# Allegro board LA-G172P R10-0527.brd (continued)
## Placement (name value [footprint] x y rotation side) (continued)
R175  10K_0201_5%  [R_0201]  124.49 15.81 90 bottom
R176  1K_0201_5%  [R_0201]  110.14 3.69 270 bottom
R178  10K_0201_5%  [R_0201]  126.02 16.39 270 bottom
R188  0_0201_5%  [R_0201]  110.9 15.12 270 bottom
R190  0_0201_5%  [R0201_0OHM]  107.35 15.12 270 bottom
R191  0_0201_5%  [R0201_0OHM]  108.19 15.12 270 bottom
R192  0_0201_5%  [R0201_0OHM]  110.22 15.12 270 bottom
R193  0_0201_5%  [R_0201]  125.25 14.54 90 bottom
R194  0_0201_5%  [R_0201]  126.02 14.54 90 bottom
R195  0_0201_5%  [R_0201]  126.78 14.54 90 bottom
R200  0_0402_5%  [R_0402]  206.67 4.98 0 top
R201  0_0201_5%  [R0201_0OHM]  108.87 3.69 270 bottom
R204  0_0603_5%  [R0603_0OHM]  202.15 15.21 90 top
R208  0_0201_5%  [R0201_0OHM]  57.35 16.48 180 bottom
R210  1K_0201_5%  [R_0201]  120.3 3.11 90 bottom
R211  0_0603_5%  [R0603_0OHM]  68.42 13.37 270 top
R213  0_0201_5%  [R0201_0OHM]  110.22 15.81 90 bottom
R216  0_0603_5%  [R0603_0OHM]  237.78 16.48 90 top
R220  100K_0201_5%  [R_0201]  174.72 64.83 90 top
R222  0_0402_5%  [R0402_0OHM]  176.25 70.25 90 top
R227  0_0603_5%  [R0603_0OHM]  21.35 24.53 225 top
R230  1K_0201_5%  [R_0201]  112.3 15.12 270 bottom
R231  1M_0402_5%  [R_0402]  97.06 68.32 90 top
R232  10K_0201_5%  [R_0201]  46.74 18.07 180 top
R236  0_0201_5%  [R_0201]  111.41 3.11 90 bottom
R238  2.2K_0201_1%  [R_0201]  132.43 80.94 90 bottom
R239  2.2K_0201_1%  [R_0201]  131.83 80.94 90 bottom
R244  0_0201_5%  [R0201_0OHM]  107.35 15.81 90 bottom
R245  100K_0201_5%  [R_0201]  129.13 80.72 270 bottom
R246  150_0201_1%  [R_0201]  112.3 16.39 270 bottom
R247  0_0201_5%  [R0201_0OHM]  108.24 3.69 270 bottom
R249  0_0201_5%  [R_0201]  124.43 3.69 270 bottom
R257  0_0201_5%  [R_0201]  119.03 3.11 90 bottom
R260  0_0201_5%  [R_0201]  116.49 3.11 90 bottom
R261  1.5K_0201_5%  [R_0201]  115.86 3.69 270 bottom
R267  1K_0201_5%  [R_0201]  119.67 3.69 270 bottom
R270  1K_0201_5%  [R_0201]  108.87 15.81 90 bottom
R271  75_0201_1%  [R_0201]  185.39 19.4 270 top
R272  330K_0201_1%  [R_0201]  206.63 60.04 90 bottom
R273  0_0201_5%  [R0201_0OHM]  205.01 60.6 0 bottom
R274  10K_0201_5%  [R_0201]  126.78 16.39 270 bottom
R283  1M_0201_5%  [R_0201]  207.86 60.62 180 bottom
R288  100K_0201_5%  [R_0201]  129.83 80.72 270 bottom
R300  0_0201_5%  [R0201_0OHM]  107.6 3.69 270 bottom
R311  1K_0201_5%  [R_0201]  122.21 3.11 90 bottom
R312  0_0201_5%  [R0201_0OHM]  108.19 15.81 90 bottom
R322  100K_0201_5%  [R_0201]  174.62 63.85 0 top
R335  0_0201_5%  [R_0201]  111.54 15.12 270 bottom
R360  0_0402_5%  [R_0402]  138.46 21.82 180 top
R374  100K_0201_5%  [R_0201]  203.42 10.3 270 top
R375  100K_0201_5%  [R_0201]  205.14 10.3 270 top
R390  0_0402_5%  [R_0402]  59.41 19.71 90 top
R410  100K_0201_5%  [R_0201]  111.54 16.39 270 bottom
R441  0_0603_5%  [R0603_0OHM]  190.15 52.17 180 top
R444  1K_0201_5%  [R_0201]  210.83 35.53 180 top
R445  1K_0201_5%  [R_0201]  210.83 34.9 180 top
R452  0_0201_5%  [R0201_0OHM]  195.8 25.84 90 top
R456  0_0201_5%  [R0201_0OHM]  199.49 52.08 270 top
R466  1K_0201_5%  [R_0201]  174.21 14.48 90 top
R470  0_0201_5%  [R0201_0OHM]  198.58 50.87 270 top
R471  0_0201_5%  [R_0201]  197.95 50.87 270 top
R529  75K_0201_5%  [R_0201]  177.77 64.58 90 bottom
R530  200_0201_1%  [R_0201]  204.02 55.15 0 bottom
R531  200_0201_1%  [R_0201]  203.33 55.15 180 bottom
R532  75K_0201_5%  [R_0201]  177.13 65.42 270 bottom
R533  0_0201_5%  [R0201_0OHM]  174.09 60.64 90 top
R534  0_0201_5%  [R_0201]  176.5 64.83 90 bottom
R544  0_0201_5%  [R_0201]  108.87 14.54 90 bottom
R545  0_0201_5%  [R_0201]  109.51 14.54 90 bottom
R600  10K_0201_5%  [R_0201]  44.89 18.07 0 top
R609  0_0201_5%  [R_0201]  210.24 33.63 0 top
R610  0_0201_5%  [R_0201]  195.17 25.84 90 top
R612  0.01_0402_1%  [R_0402]  161.49 76.26 0 bottom
R614  51_0201_5%  [R_0201]  134.97 27.44 270 bottom
R616  100K_0201_5%  [R_0201]  174.62 63.22 0 top
R617  20K_0201_5%  [R_0201]  174.09 62.5 270 top
R618  10K_0201_5%  [R_0201]  160.05 76.3 270 bottom
R620  0_0402_5%  [R0402_0OHM]  177.07 70.25 90 top
R621  10K_0201_5%  [R_0201]  122.09 79.83 0 bottom
R622  10K_0201_5%  [R_0201]  126.35 77.99 270 bottom
R623  200K_0201_5%  [R_0201]  126.92 77.4 90 bottom
R624  200K_0201_5%  [R_0201]  122.68 80.4 180 bottom
R626  0.01_0603_1%  [R_0603]  218.41 15.53 180 top
R627  47K_0201_5%  [R_0201]  123.35 78 180 bottom
R628  47K_0201_5%  [R_0201]  127.49 77.4 90 bottom
R629  100K_0201_5%  [R_0201]  60.26 11.97 180 top
R633  0_0201_5%  [R0201_0OHM]  90.28 65.07 90 top
R634  0_0402_5%  [R_0402]  162.39 75.38 180 bottom
R636  0_0201_5%  [R0201_0OHM]  66.29 18.93 0 top
R638  0_0402_5%  [R0402_0OHM]  60.17 19.71 90 top
R644  0_0201_5%  [R_0201]  117.13 3.11 90 bottom
R648  33_0201_5%  [R_0201]  215.44 6.79 90 top
R649  10K_0201_5%  [R_0201]  209.28 12.09 0 top
R651  0_0201_5%  [R0201_0OHM]  128.15 77.4 90 bottom
R652  0_0201_5%  [R0201_0OHM]  125.78 77.4 90 bottom
R655  0_0402_5%  [R_0402]  160.73 75.36 90 bottom
R656  10K_0201_5%  [R_0201]  215.44 5.56 90 top
R658  100K_0201_5%  [R_0201]  123.98 77.4 90 bottom
R660  51_0201_5%  [R_0201]  135.61 27.44 270 bottom
R666  100K_0201_5%  [R_0201]  265.23 25.59 270 top
R667  100K_0201_5%  [R_0201]  266.38 25.59 270 top
R669  0_0603_5%  [R0603_0OHM]  269.17 22.06 0 top
R670  0_0603_5%  [R0603_0OHM]  265.3 19.33 180 top
R672  0_0201_5%  [R0201_0OHM]  174.09 64.83 90 top
R677  1M_0201_5%  [R_0201]  125.19 77.99 270 bottom
R678  1M_0201_5%  [R_0201]  197.2 50.29 90 top
R679  1M_0201_5%  [R_0201]  210.37 42.01 0 top
R680  1M_0201_5%  [R_0201]  195.17 25.22 270 top
R681  1M_0201_5%  [R_0201]  210.24 32.99 0 top
R687  0_0402_5%  [R_0402]  206.67 4.19 0 top
R688  0_0402_5%  [R_0402]  206.67 11.71 0 top
R694  0_0402_5%  [R_0402]  171.93 65.96 180 top
R700  49.9_0201_1%  [R_0201]  216.08 20.57 270 bottom
R701  49.9_0201_1%  [R_0201]  215.5 20.57 270 bottom
R702  0_0201_5%  [R0201_0OHM]  214.29 20.59 270 bottom
R703  49.9_0201_1%  [R_0201]  212.44 20.57 270 bottom
R704  10K_0201_5%  [R_0201]  169.32 65.59 90 top
R709  10K_0201_5%  [R_0201]  157.7 77.85 90 bottom
R710  680_0201_5%  [R_0201]  159.23 80.45 90 bottom
R716  0_0805_5%  [R0805_0OHM]  42.79 14.26 180 top
R720  0_0402_5%  [R0402_0OHM]  171.93 67.18 180 top
R724  100K_0201_5%  [R_0201]  210.24 34.26 0 top
R725  0_0201_5%  [R_0201]  120.94 3.69 270 bottom
R726  0_0201_5%  [R_0201]  121.57 3.69 270 bottom
R747  0_0201_5%  [R0201_0OHM]  206.84 7.59 0 top
R787  0_0201_5%  [R0201_0OHM]  211.03 52.86 270 top
R789  150_0201_1%  [R_0201]  199.19 13.44 0 top
R800  0_0201_5%  [R0201_0OHM]  63.04 13.94 0 top
R801  0_0201_5%  [R_0201]  63.04 14.57 0 top
R808  0_0201_5%  [R0201_0OHM]  62.44 15.62 0 top
R931  2.1K_0402_1%  [R_0402]  90.19 66.74 180 top
R932  2.1K_0402_1%  [R_0402]  90.19 67.6 180 top
R1000  100K_0201_1%  [R_0201]  212.26 30.08 90 top
R1015  0_0201_5%  [R0201_0OHM]  131.83 79.25 90 bottom
R1016  0_0201_5%  [R0201_0OHM]  132.43 79.25 90 bottom
R1095  0_0402_5%  [R0402_0OHM]  189.88 44.59 0 top
R1096  0_0402_5%  [R0402_0OHM]  189.88 43.83 0 top
R1133  120K_0201_1%  [R_0201]  211.07 30.08 0 top
R1134  200K _0201_1%  [R_0201]  211.66 30.67 180 top
R1135  0_0201_1%  [R_0201]  211.08 29.5 0 top
R1136  100K_0201_1%  [R_0201]  212.26 28.9 90 top
R1141  100K_0201_1%  [R_0201]  196.93 4.66 180 top
R1142  100K_0201_1%  [R_0201]  197.66 5.32 270 top
R1143  100K_0201_1%  [R_0201]  198.83 4.8 180 top
R1150  0_0201_5%  [R0201_0OHM]  211.08 28.91 0 top
R2745  100K_0201_1%  [R_0201]  177.93 16.93 180 top
R2751  0_0402_5%  [R_0402]  179.05 11.15 180 top
R5717  0_0603_5%  [R0603_0OHM]  214.74 14.27 0 top
R5768  10K_0402_5%  [R_0402]  182.01 15.21 0 top
R5769  1M_0402_5%~D  [R_0402]  181.15 17.37 180 top
R5779  0_0402_5%  [R0402_0OHM]  179.42 17.42 90 top
R6048  0_0603_5%  [R0603_0OHM]  206.22 13.88 0 top
R6089  0_0402_5%  [R0402_0OHM]  275.17 26.71 0 top
R6090  0_0402_5%  [R0402_0OHM]  275.17 25.88 0 top
R6114  0_0201_5%  [R0201_0OHM]  161.07 77.85 90 bottom
R6115  0_0201_5%  [R0201_0OHM]  160.05 77.85 90 bottom
R6116  0_0201_5%  [R0201_0OHM]  155.53 80.08 90 bottom
R6117  0_0201_5%  [R0201_0OHM]  156.17 80.08 90 bottom
R6118  0_0201_5%  [R0201_0OHM]  157.7 80.45 90 bottom
R6128  2.2K_0201_5%  [R_0201]  160.05 79.77 270 bottom
R6129  2.2K_0201_5%  [R_0201]  161.07 79.77 270 bottom
R6133  0_0603_5%  [R0603_0OHM]  200.63 25.94 180 top
R6135  0_0603_5%  [R0603_0OHM]  187.61 16.8 0 top
R6136  0_0603_5%  [R_0603]  214.47 45.19 180 top
R6137  100K_0201_5%  [R_0201]  173.45 61.23 270 top
R6141  0_0201_5%  [R0201_0OHM]  154.67 80.19 90 bottom
R6142  0_0201_5%  [R0201_0OHM]  158.53 80.45 90 bottom
R6143  1K_0201_5%  [R_0201]  109.51 15.81 90 bottom
R6152  0_0201_5%  [R0201_0OHM]  204.86 50.27 180 top
R6155  0_0201_5%  [R_0201]  178.11 58.27 0 bottom
R6157  10K_0201_5%  [R_0201]  157.7 79.77 270 bottom
R6161  0_0603_5%  [R0603_0OHM]  170.78 69.25 90 top
R6162  10K_0201_5%  [R_0201]  168.18 65.59 90 top
R6163  0_0201_5%  [R0201_0OHM]  168.75 65.59 90 top
R6164  0_0201_5%  [R0201_0OHM]  217.09 47.12 0 top
R6166  0_0201_5%  [R0201_0OHM]  206.89 25.88 180 top
R6168  0_0201_5%  [R_0201]  175.99 64.83 90 top
R6169  0_0201_5%  [R0201_0OHM]  245.03 17.74 180 top
R6170  0_0201_5%  [R0201_0OHM]  195.71 52.81 180 top
R6171  0_0201_5%  [R_0201]  265.81 25.59 270 top
R6172  4.7K_0201_5%  [R_0201]  179.2 33.88 180 bottom
R6173  4.7K_0201_5%  [R_0201]  179.2 33.25 180 bottom
R6174  4.7K_0201_5%  [R_0201]  183.65 41.38 180 bottom
R6175  4.7K_0201_5%  [R_0201]  183.65 40.74 180 bottom
R6181  0_0201_5%  [R0201_0OHM]  100.34 7.21 180 top
R6182  0_0603_5%  [R0603_0OHM]  94.65 5.69 180 top
R6183  100K_0201_5%  [R_0201]  188.44 10.98 90 top
R6184  100K_0201_5%  [R_0201]  217.09 46.52 0 top
R6185  100K_0201_5%  [R_0201]  206.89 26.52 180 top
R6193  0_0201_5%  [R0201_0OHM]  189.01 10.98 90 top
R6194  100K_0201_5%  [R_0201]  175.36 64.83 90 top
R6199  0_0201_5%  [R0201_0OHM]  271.05 20.53 180 top
R6204  100K_0201_5%  [R_0201]  175.06 16.86 0 top
R6205  0_0201_5%  [R_0201]  66.29 18.36 0 top
R6206  0_0201_5%  [R_0201]  67.53 18.35 90 top
R6207  0_0201_5%  [R_0201]  159.23 79.18 90 bottom
R6208  100K_0201_5%  [R_0201]  177.97 39.64 90 top
RA1  2.2K_0201_5%  [R_0201]  30.26 21.88 180 top
RA2  2.2K_0201_5%  [R_0201]  31.44 21.12 180 bottom
RA3  20_0201_1%  [R_0201]  14.79 69.47 180 top
RA6  20_0201_1%  [R_0201]  7.81 75.12 270 bottom
RA8  1K_0201_5%  [R_0201]  22.49 22.45 180 top
RA9  1K_0201_5%  [R_0201]  23.17 23.09 0 top
RA10  100K_0201_5%  [R_0201]  24.8 19.44 270 top
RA13  100K_0201_1%  [R_0201]  26.64 11.24 90 top
RA14  200K _0201_1%  [R_0201]  25.98 11.21 180 top
RA17  33_0201_5%  [R_0201]  34.77 13.66 270 top
RA18  0_0402_5%  [R0402_0OHM]  37.69 13.87 90 top
RA21  1K_0201_5%  [R_0201]  29.14 10.77 0 top
RA22  0_0402_5%  [R0402_0OHM]  20.47 62.51 45 bottom
RA23  0_0402_5%  [R0402_0OHM]  23.01 18.58 0 bottom
RA25  0_0402_5%  [R0402_0OHM]  35.28 15.71 90 bottom
RA27  0_0201_5%  [R0201_0OHM]  21.9 21.18 0 top
RA28  0_0201_5%  [R0201_0OHM]  23.17 20.55 0 top
RA29  0_0402_5%  [R0402_0OHM]  31.66 9.49 90 top
RA30  1K_0201_5%  [R_0201]  23.76 22.45 180 top
RA36  0_0402_5%  [R_0402]  33.32 10.32 180 top
RA41  0_0402_5%  [R_0402]  36.93 13.87 90 top
RA57  100K_0201_5%  [R_0201]  29.73 10.2 180 top
RA58  0_0201_5%  [R0201_0OHM]  32.84 11.09 180 top
RA62  22_0201_5%  [R_0201]  32.84 11.97 180 top
RA63  0_0201_5%  [R_0201]  28.48 11.05 90 top
RA64  10K_0201_5%  [R_0201]  28.1 21.14 90 top
RA65  10K_0201_5%  [R_0201]  6.29 6.95 180 top
RA66  0_0201_5%  [R_0201]  28.48 9.84 90 top
RC1  150_0201_1%  [R_0201]  145.28 22.13 0 top
RC2  49.9_0201_1%  [R_0201]  137.38 26.86 90 bottom
RC3  150_0201_1%  [R_0201]  133.32 24.57 90 bottom
RC8  100_0201_1%  [R_0201]  122.93 23.87 180 top
RC12  100_0201_1%  [R_0201]  130.02 50.1 90 top
RC13  100_0201_1%  [R_0201]  130.65 50.1 90 top
RC14  100_0201_1%  [R_0201]  129.26 50.1 90 top
RC15  150_0201_1%  [R_0201]  172.65 45.69 0 bottom
RC16  200_0201_1%  [R_0201]  164.31 41.54 270 bottom
RC17  200_0201_1%  [R_0201]  173.41 36.55 0 bottom
RC20  200_0201_1%  [R_0201]  159.99 45.02 90 bottom
RC120  0_0603_5%  [R0603_0OHM]  179.36 35.72 0 top
RC139  0_0603_5%  [R0603_0OHM]  171.74 60.81 180 top
RC145  51_0201_5%  [R_0201]  134.08 22.11 270 top
RC146  51_0201_5%  [R_0201]  130.91 26.73 90 bottom
RC147  100K_0201_5%  [R_0201]  221 45.07 180 top
RC150  100_0201_5%  [R_0201]  132.05 22.11 270 top
RC151  51_0201_5%  [R_0201]  131.48 22.11 270 top
RC165  0_0402_5%  [R_0402]  181.27 38.33 180 top
RC168  0_0402_5%  [R0402_0OHM]  181.27 39.09 180 top
RC180  51_0201_5%  [R_0201]  133.45 26.73 90 bottom
RC181  51_0201_5%  [R_0201]  132.81 26.73 90 bottom
RC201  51_0201_5%  [R_0201]  132.18 26.73 90 bottom
RC202  100_0201_5%  [R_0201]  129.76 22.11 270 top
RC203  51_0201_5%  [R_0201]  133.32 22.11 270 top
RC222  49.9K_0201_1%  [R_0201]  176.84 32.99 0 top
RC223  49.9K_0201_1%  [R_0201]  176.84 34.14 0 top
RC226  0_0201_5%  [R0201_0OHM]  149.19 15.56 90 top
RC244  10K_0201_5%  [R_0201]  185.35 32.99 0 top
RC247  1K_0201_5%  [R_0201]  172.35 18.26 180 top
RC254  0_0201_5%  [R_0201]  158.64 47.76 270 bottom
RC255  0_0201_5%  [R0201_0OHM]  159.2 47.76 270 bottom
RC336  10_0201_1%  [R_0201]  162.78 50.1 90 top
RC338  10K_0201_5%  [R_0201]  160.43 47.42 180 bottom
RC339  10K_0201_5%  [R_0201]  158.08 47.76 270 bottom
RC344  51_0201_5%  [R_0201]  132.68 22.11 270 top
RC351  0_0201_5%  [R_0201]  147.04 21.14 90 top
RC367  10_0201_1%  [R_0201]  160.88 50.1 90 top
RC368  10_0201_1%  [R_0201]  161.51 50.1 90 top
RC369  10_0201_1%  [R_0201]  162.15 50.1 90 top
RC430  0_0201_5%  [R0201_0OHM]  186.43 33.97 90 top
RC432  1K_0201_5%  [R_0201]  185.86 33.97 90 top
RC433  8.2K_0201_5%  [R_0201]  187.13 32.36 0 top
RC434  8.2K_0201_5%  [R_0201]  189.45 31.77 90 top
RC503  22_0201_1%  [R_0201]  194.06 61.31 180 bottom
RC504  22_0201_1%  [R_0201]  194.06 61.95 180 bottom
RC505  0_0402_5%  [R0402_0OHM]  214.99 18.32 180 top
RC508  1M_0201_5%  [R_0201]  214.13 17.6 0 top
RC569  49.9_0201_1%  [R_0201]  162.4 49.97 270 bottom
RC582  0_0402_5%  [R_0402]  177.77 37.25 180 bottom
RC583  0_0402_5%  [R0402_0OHM]  174.95 37.6 0 bottom
RC587  0_0603_5%  [R0603_0OHM]  181.9 33.06 90 top
RC589  0.1_0402_1%  [R_0402]  178.4 35.46 90 top
RC592  0_0603_5%  [R0603_0OHM]  137.7 19.66 0 top
RC595  100K_0201_5%  [R_0201]  177.93 32.61 180 bottom
RC601  0_0201_5%  [R0201_0OHM]  111.94 20.04 0 top
RC602  56_0201_5%  [R_0201]  110.74 20.04 0 top
RC603  0_0201_5%  [R0201_0OHM]  111.94 19.34 0 top
RC604  100_0201_1%  [R_0201]  110.74 19.34 0 top
RC605  0_0201_5%  [R0201_0OHM]  111.94 20.74 0 top
RC606  100_0201_5%  [R_0201]  110.74 20.74 0 top
RC609  10K_0201_5%  [R_0201]  138.45 3.5 90 top
RC610  10K_0201_5%  [R_0201]  137.86 3.5 90 top
RC611  10K_0201_5%  [R_0201]  139.03 3.5 90 top
RC612  10K_0201_5%  [R_0201]  137.28 3.5 90 top
RC614  499_0201_1%  [R_0201]  125.13 20.57 90 top
RC615  100K_0201_5%  [R_0201]  185.83 27.56 90 top
RC616  100K_0201_5%  [R_0201]  189.45 28.71 270 top
RC617  100K_0201_5%  [R_0201]  187.71 31.72 180 top
RC619  0_0201_5%  [R0201_0OHM]  110.55 20.29 0 bottom
RC623  0_0201_5%  [R_0201]  111.82 19.53 0 bottom
RC624  0_0201_5%  [R0201_0OHM]  181.92 39.85 0 top
RC626  100K_0201_5%  [R_0201]  111.82 20.29 0 bottom
RC627  0_0201_5%  [R_0201]  185.77 38.49 270 top
RC630  0_0603_5%  [R0603_0OHM]  135.16 19.66 0 top
RC631  100K_0201_5%  [R_0201]  149.83 16.14 270 top
RC634  0_0201_5%  [R_0201]  153.51 17.46 90 top
RC636  0_0201_5%  [R0201_0OHM]  153.51 19.32 270 top
RC639  0_0603_5%  [R0603_0OHM]  129.76 16.93 90 top
RC640  0_0201_5%  [R0201_0OHM]  110.12 49.63 180 top
RC643  0_0603_5%  [R0603_0OHM]  105.7 46.2 0 top
RC644  0_0201_5%  [R_0201]  173.62 18.26 180 top
RC647  1K_0201_5%  [R_0201]  170.24 18.9 0 top
RC648  100K_0201_5%  [R_0201]  177.45 41.18 180 bottom
RC651  0_0201_5%  [R0201_0OHM]  203.99 9.71 90 top
RC655  49.9K_0201_1%  [R_0201]  176.84 34.71 0 top
RC656  49.9K_0201_1%  [R_0201]  176.84 33.56 0 top
RC657  0_0201_5%  [R0201_0OHM]  204.57 9.71 90 top
RC659  0_0603_5%  [R0603_0OHM]  128.43 20.1 0 top
RC663  10K_0201_5%  [R_0201]  141.12 6.46 90 top
RC664  10K_0201_5%  [R_0201]  140.53 6.46 90 top
RC665  1K_0201_5%  [R_0201]  186.41 46.94 270 bottom
RC666  1K_0201_5%  [R_0201]  187.04 46.94 270 bottom
RC667  1K_0201_5%  [R_0201]  173.13 53.61 270 bottom
RC668  1K_0201_5%  [R_0201]  172.56 53.61 270 bottom
RC671  10K_0201_5%  [R_0201]  169.77 35.47 270 bottom
RC672  1K_0201_5%  [R_0201]  179.42 40.23 180 top
RC673  1K_0201_5%  [R_0201]  179.42 40.87 180 top
RC679  10K_0201_5%  [R_0201]  177.93 41.5 180 top
RC680  10K_0201_5%  [R_0201]  179.33 41.5 180 top
RC682  10K_0201_5%  [R_0201]  159.35 49.8 270 bottom
RC683  0_0201_5%  [R0201_0OHM]  124.54 38.93 90 bottom
RC684  0_0201_5%  [R0201_0OHM]  124.54 40.13 90 bottom
RC685  0_0201_5%  [R0201_0OHM]  146.08 19.3 90 top
RC686  0_0201_5%  [R0201_0OHM]  145.51 19.3 90 top
RC687  10K_0201_5%  [R_0201]  161.26 43.57 270 bottom
RC688  0_0201_5%  [R0201_0OHM]  178.75 42.77 0 top
RC689  0_0201_5%  [R0201_0OHM]  159.35 42.33 0 bottom
RC690  0_0201_5%  [R0201_0OHM]  178.75 42.14 0 top
RC691  20K_0201_5%  [R_0201]  177.35 33.88 0 bottom
RC692  20K_0201_5%  [R_0201]  177.35 33.25 0 bottom
RC693  20K_0201_5%  [R_0201]  183.65 42.01 180 bottom
RC694  20K_0201_5%  [R_0201]  183.65 40.11 180 bottom
RC695  0_0201_5%  [R0201_0OHM]  190.34 49.92 270 top
RC696  0_0402_5%  [R0402_0OHM]  178.2 39.72 0 bottom
RC697  0_0201_5%  [R0201_0OHM]  177.73 53.69 0 top
RC698  0_0201_5%  [R_0201]  177.58 52.26 90 top
RC699  0_0201_5%  [R0201_0OHM]  177.01 52.26 90 top
RC700  100K_0201_5%  [R_0201]  109.86 20.29 180 bottom
RC701  100K_0201_5%  [R_0201]  154.3 19.66 0 top
RC702  0_0201_5%  [R0201_0OHM]  175.65 16.23 180 top
RC703  0_0201_5%  [R0201_0OHM]  175.65 15.59 180 top
RC704  0_0201_5%  [R0201_0OHM]  175.65 17.5 180 top
RC711  75K_0201_1%  [R_0201]  163.42 50.1 90 top
RC712  75K_0201_1%  [R_0201]  164.05 50.1 90 top
RC717  10K_0201_5%  [R_0201]  156.43 50.68 270 top
RC718  0_0603_5%  [R0603_0OHM]  147.8 21.44 0 top
RC723  10K_0201_5%  [R_0201]  134.08 28 90 bottom
RC724  10K_0201_5%  [R_0201]  134.08 27.32 270 bottom
RC727  0_0201_5%  [R_0201]  176.78 40.26 0 top
RC730  0_0201_5%  [R_0201]  152.85 15.66 180 top
RC731  0_0201_5%  [R0201_0OHM]  151.06 15.66 0 top
RC734  33_0201_5%  [R_0201]  165.83 44.64 270 bottom
RC735  100K_0201_5%  [R_0201]  184.12 35.79 180 top
RC736  0_0402_5%  [R0402_0OHM]  92.91 65.91 270 top
RC737  1M_0201_5%  [R_0201]  93.95 64.27 270 top
RC738  10K_0201_5%  [R_0201]  184.23 40.38 315 top
RC739  10K_0201_5%  [R_0201]  184.18 42.82 180 top
RC740  10K_0201_5%  [R_0201]  183.13 37.95 0 bottom
RC741  10K_0201_5%  [R_0201]  183.56 41.44 270 top
RC742  10K_0201_5%  [R_0201]  183.6 42.23 0 top
RC743  10K_0201_5%  [R_0201]  183.71 38.71 180 bottom
RC744  20K_0201_5%  [R_0201]  181.6 43.15 0 top
RC745  0_0402_5%  [R0402_0OHM]  236.51 16.94 270 top
RC746  0_0201_5%  [R_0201]  181.86 37.02 90 top
RC747  0_0402_5%  [R0402_0OHM]  167.9 43.22 0 bottom
RC748  0_0201_5%  [R_0201]  127.81 30.48 180 bottom
RC749  0_0201_5%  [R_0201]  123.4 24.04 45 bottom
RC750  0_0201_5%  [R_0201]  123.81 23.64 45 bottom
RC751  10K_0201_5%  [R_0201]  191.33 31.47 180 bottom
RC752  10K_0201_5%  [R_0201]  191.33 30.83 180 bottom
RD1  240_0201_1%  [R_0201]  159.16 52 90 top
RD2  240_0201_1%  [R_0201]  162.19 52.61 180 top
RD3  240_0201_1%  [R_0201]  130.88 71.08 270 top
RD4  240_0201_1%  [R_0201]  128.47 71.08 270 top
RD21  240_0201_1%  [R_0201]  148.34 52.55 180 top
RD22  240_0201_1%  [R_0201]  144.84 52.55 0 top
RD23  240_0201_1%  [R_0201]  113.51 71.19 270 top
RD24  240_0201_1%  [R_0201]  115.92 71 270 top
RD25  0_0201_5%  [R0201_0OHM]  167.65 58.39 180 top
RD26  0_0201_5%  [R_0201]  167.06 57.76 0 top
RD27  0_0201_5%  [R0201_0OHM]  167.65 63.35 180 top
RD28  0_0201_5%  [R_0201]  167.06 63.98 0 top
RD29  0_0201_5%  [R0201_0OHM]  153.35 58.46 0 top
RD30  0_0201_5%  [R_0201]  153.35 57.82 0 top
RD31  0_0201_5%  [R0201_0OHM]  153.35 64.36 0 top
RD32  0_0201_5%  [R_0201]  153.35 64.93 0 top
RD33  0_0201_5%  [R0201_0OHM]  123.26 65.47 270 top
RD34  0_0201_5%  [R_0201]  122.65 65.45 180 top
RD35  0_0201_5%  [R0201_0OHM]  123.29 59.27 90 top
RD36  0_0201_5%  [R_0201]  123.27 58.65 180 top
RD37  0_0201_5%  [R0201_0OHM]  108.43 63.51 270 top
RD38  0_0201_5%  [R_0201]  108.41 64.12 180 top
RD39  0_0201_5%  [R0201_0OHM]  108.43 60.17 90 top
RD40  0_0201_5%  [R_0201]  108.43 59.54 180 top
RD41  0_0201_5%  [R_0201]  81.92 71.22 180 top
RD42  0_0201_5%  [R0201_0OHM]  82.61 71.22 0 top
RD43  0_0201_5%  [R_0201]  92.22 65.67 270 top
RD44  0_0201_5%  [R_0201]  91.03 65.67 0 top
RD45  0_1206_5%  [R_1206]  103.92 60.81 0 top
RD46  0_1206_5%  [R_1206]  106.52 56.49 90 top
RD300  1M_0201_5%  [R_0201]  83.75 64.93 0 top
RD400  0_0402_5%  [R0402_0OHM]  82.88 65.07 90 top
RE1  10K_0201_5%  [R_0201]  204.86 55.09 180 top
RE10  0_0201_5%  [R_0201]  175.48 18.98 90 top
RE14  100K_0201_5%  [R_0201]  189.62 48.11 180 top
RE15  0_0201_5%  [R_0201]  187.76 48.11 0 top
RE21  100K_0201_5%  [R_0201]  189.03 48.74 0 top
RE22  0_0201_5%  [R_0201]  187.76 48.74 0 top
RE29  100K_0201_5%  [R_0201]  175.48 20.25 90 top
RE48  100K_0201_5%  [R_0201]  210.28 60.21 270 bottom
RE49  0_0603_5%  [R0603_0OHM]  202.92 58.84 90 top
RE87  100K_0201_5%  [R_0201]  198.34 53.66 90 top
RE93  10K_0201_5%  [R_0201]  203 55.09 0 top
RE95  100K_0201_5%  [R_0201]  203.04 63.5 90 top
RE96  100K_0201_5%  [R_0201]  219.59 55.35 180 top
RE97  100K_0201_5%  [R_0201]  207.76 60 270 bottom
RE98  100K_0201_5%  [R_0201]  210.41 64.32 90 bottom
RE99  100K_0201_5%  [R_0201]  214.85 62.62 270 bottom
RE100  100K_0201_5%  [R_0201]  215.87 62.62 270 bottom
RE101  100K_0201_5%  [R_0201]  215.23 64.27 270 bottom
RE102  100K_0201_5%  [R_0201]  214.6 64.27 270 bottom
RE106  0_0402_5%  [R0402_0OHM]  206.94 65.39 90 bottom
RE108  100K_0201_5%  [R_0201]  214.22 62.04 90 bottom
RE109  100K_0201_5%  [R_0201]  211.11 62.23 90 bottom
RE111  2.2K_0201_5%  [R_0201]  207.23 54.11 270 top
RE112  2.2K_0201_5%  [R_0201]  206.6 54.11 270 top
RE113  100_0201_5%  [R_0201]  203.17 62.04 90 top
RE115  43K_0402_1%  [R_0402]  208 53.24 90 top
RE122  100K_0201_5%  [R_0201]  216.55 53.53 90 top
RE123  100K_0201_5%  [R_0201]  219.46 63.93 180 top
RE124  10K_0201_1%  [R_0201]  216.42 64.87 180 bottom
RE125  300_0402_5%  [R_0402]  208.76 52.37 270 top
RE126  300_0402_5%  [R_0402]  208.76 54.15 270 top
RE130  100K_0201_5%  [R_0201]  215.87 64.27 270 bottom
RE133  100K_0201_5%  [R_0201]  203.72 64.74 180 top
RE137  100K_0201_5%  [R_0201]  210.03 68.13 90 top
RE142  100K_0201_5%  [R_0201]  209.39 68.13 90 top
RE147  0_0201_5%  [R0201_0OHM]  214.35 59.57 270 bottom
RE152  1K_0201_5%  [R_0201]  203.13 65.51 0 top
RE153  43_0402_5%  [R_0402]  218.97 57.31 0 top
RE154  100K_0201_5%  [R_0201]  204.99 65.51 180 top
RE156  100K_0201_5%  [R_0201]  219.01 53.44 0 top
RE157  100K_0201_5%  [R_0201]  200.97 61.19 0 top
RE158  100_0402_1%  [R_0402]  218.97 60.93 0 top
RE159  10K_0201_5%  [R_0201]  210.41 54.11 270 top
RE160  100K_0201_5%  [R_0201]  205.77 53.53 90 top
RE164  100_0201_1%  [R_0201]  218.88 50.52 0 top
RE172  33_0201_5%  [R_0201]  212.11 69.58 0 top
RE178  0_0402_5%  [R_0402]  208.58 68.17 180 top
RE183  10K_0201_1%  [R_0201]  201.18 67.54 180 top
RE184  100K_0201_5%  [R_0201]  201.61 64.49 0 top
RE185  0_0201_5%  [R0201_0OHM]  219.01 54.08 0 top
RE186  0_0201_5%  [R_0201]  204.4 57.25 0 top
RE187  1K_0201_5%  [R_0201]  201.61 63.85 0 top
RE193  0_0201_5%  [R_0201]  211.55 67.31 90 bottom
RE194  2K_0402_5%  [R_0402]  219.88 59.18 180 top
RE199  1.58K_0402_1%  [R_0402]  218.97 66.78 0 top
RE200  10_0201_1%  [R_0201]  229.52 2.39 0 top
RE201  10K_0201_5%  [R_0201]  226.26 10.29 270 top
RE202  10K_0201_5%  [R_0201]  227.94 10.41 270 top
RE203  10K_0201_5%  [R_0201]  227.38 10.41 270 top
RE204  100K_0201_5%  [R_0201]  229.65 10.41 270 top
RE205  10K_0201_5%  [R_0201]  229.08 9.83 90 top
RE206  0_0201_5%  [R_0201]  228.51 10.41 270 top
RE208  100K_0201_5%  [R_0201]  219.59 55.98 180 top
RE209  0_0201_5%  [R0201_0OHM]  226.82 9.7 90 top
RE210  10K_0201_5%  [R_0201]  230.21 9.83 90 top
RE211  10K_0201_5%  [R_0201]  230.77 9.83 90 top
RE212  10K_0201_5%  [R_0201]  231.34 9.83 90 top
RE213  10K_0201_5%  [R_0201]  231.91 9.55 90 top
RE215  8.2K_0201_1%  [R_0201]  201.56 60.58 180 top
RE219  2.2K_0201_5%  [R_0201]  197.71 56.96 90 top
RE237  100K_0201_5%  [R_0201]  64.22 15.62 180 top
RE244  100K_0201_5%  [R_0201]  210.66 68.13 90 top
RE245  0_0201_5%  [R_0201]  213.58 54.11 270 top
RE247  100K_0201_5%  [R_0201]  204.4 64.74 0 top
RE248  0_0201_5%  [R0201_0OHM]  212.69 61.28 90 bottom
RE305  0_0402_5%  [R0402_0OHM]  86.41 58.27 90 top
RE312  1M_0201_5%  [R_0201]  87.19 58.3 270 top
RE321  0_0201_1%  [R_0201]  176.66 62.46 180 top
RE322  0_0201_1%  [R_0201]  174.81 62.46 0 top
RE402  0_0402_5%  [R0402_0OHM]  212.85 25.61 90 top
RE405  0_0402_5%  [R0402_0OHM]  26.97 3.45 90 top
RE411  0_0402_5%  [R0402_0OHM]  213.43 52.36 0 top
RE412  1M_0201_5%  [R_0201]  212.06 26.68 270 top
RE417  0_0402_5%  [R0402_0OHM]  266.02 9.38 0 top
RE426  100K_0201_5%  [R_0201]  210.92 60.21 270 bottom
RE428  0_0201_5%  [R0201_0OHM]  210.98 67.31 90 bottom
RE431  0_0201_5%  [R0201_0OHM]  214.85 54.11 270 top
RE445  2.2K_0201_5%  [R_0201]  208.25 64.91 270 bottom
RE446  2.2K_0201_5%  [R_0201]  209.52 64.91 270 bottom
RE448  0_0201_5%  [R0201_0OHM]  204.86 55.85 180 top
RE449  100K_0201_5%  [R_0201]  207.87 61.28 90 bottom
RE451  10K_0201_1%  [R_0201]  199.49 50.87 270 top
RE457  0_0201_5%  [R_0201]  202.15 53.1 270 top
RE458  2.2K_0201_5%  [R_0201]  211.93 61.95 90 bottom
RE459  2.2K_0201_5%  [R_0201]  211.04 64.91 270 bottom
RE460  0_0201_5%  [R_0201]  187.32 45.06 0 top
RE461  0_0201_5%  [R0201_0OHM]  212.95 54.11 270 top
RE462  0_0201_5%  [R0201_0OHM]  209.65 70.29 90 top
RE463  0_0201_5%  [R0201_0OHM]  212.19 71 270 top
RE464  0_0201_5%  [R0201_0OHM]  202.15 53.78 90 top
RE467  0_0201_5%  [R0201_0OHM]  219.46 64.5 180 top
RE468  0_0201_5%  [R0201_0OHM]  219.46 65.13 180 top
RE469  100K_0201_5%  [R_0201]  210.47 62.23 90 bottom
RE470  100K_0201_5%  [R_0201]  208.88 64.91 270 bottom
RE471  0_0201_5%  [R0201_0OHM]  219.59 56.62 180 top
RE472  100K_0201_5%  [R_0201]  211.04 53.53 90 top
RE473  100K_0201_5%  [R_0201]  212.31 53.53 90 top
RE475  100K_0201_5%  [R_0201]  219.49 61.61 180 top
RE476  0_0201_5%  [R0201_0OHM]  215.41 53.53 90 top
RE477  0_0201_5%  [R0201_0OHM]  197.71 55.69 90 top
RE478  100K_0201_1%  [R_0201]  212.31 52.86 270 top
RE479  390K_0402_1%  [R_0402]  213.25 48.92 0 top
RE480  1M_0201_1%  [R_0201]  216.16 49 180 top
RE481  10K_0201_5%  [R_0201]  219.01 54.71 0 top
RE482  0_0201_5%  [R0201_0OHM]  217.33 53.53 90 top
RE483  2.2K_0201_5%  [R_0201]  211.93 63.69 90 bottom
RE484  2.2K_0201_5%  [R_0201]  212.57 63.69 90 bottom
RE485  0_0201_5%  [R_0201]  219.53 67.54 180 top
RE486  100K_0201_5%  [R_0201]  203.8 58.39 270 top
RE487  0_0201_5%  [R_0201]  204.99 56.5 180 top
RE488  100K_0201_5%  [R_0201]  142.87 7.04 270 top
RE489  0_0402_5%  [R0402_0OHM]  95.39 51.57 0 top
RE490  0_0402_5%  [R0402_0OHM]  200.56 6.14 180 top
RE491  1M_0201_5%  [R_0201]  198.83 5.42 180 top
RE492  0_0201_5%  [R0201_0OHM]  220.68 65.32 0 top
RE493  10K_0201_5%  [R_0201]  220.76 52.83 90 top
RE494  0_0201_5%  [R_0201]  204.73 67.92 180 top
RE520  10M_0201_1%  [R_0201]  217.58 72.43 180 top
RE521  100K_0201_5%  [R_0201]  214.78 72.43 0 top
RE522  100K_0201_5%  [R_0201]  211.69 52.86 270 top
RE523  0_0201_5%  [R_0201]  252.67 10.7 90 top
RE524  0_0201_5%  [R_0201]  252.67 11.9 90 top
RE525  240K_0402_5%  [R_0402]  204.82 66.32 90 top
RE526  100K_0201_5%  [R_0201]  214.51 60.21 90 bottom
RH1  100_0201_1%  [R_0201]  171.55 22.11 270 top
RH4  49.9_0201_1%  [R_0201]  159.99 43.57 270 bottom
RH5  49.9_0201_1%  [R_0201]  177.98 24.36 0 top
RH6  49.9_0201_1%  [R_0201]  125.17 31.07 270 bottom
RH7  49.9_0201_1%  [R_0201]  127.23 31.06 0 bottom
RH8  10K_0201_5%  [R_0201]  170.28 22.11 270 top
RH9  10K_0201_5%  [R_0201]  183.1 31.44 270 top
RH10  113_0201_1%  [R_0201]  170.91 22.11 270 top
RH11  0_0201_5%  [R0201_0OHM]  147.67 50.19 90 top
RH12  470_0201_1%  [R_0201]  167.65 58.96 180 top
RH13  0_0201_5%  [R0201_0OHM]  131.67 50.68 270 top
RH14  0_0201_5%  [R_0201]  177.49 30.59 0 top
RH15  0_0201_5%  [R_0201]  177.49 29.96 0 top
RH16  10M_0201_1%  [R_0201]  171.33 51.34 180 top
RH17  200K _0201_1%  [R_0201]  178.67 29.98 90 top
RH23  49.9_0201_1%  [R_0201]  216.66 19.99 90 bottom
RH24  49.9_0201_1%  [R_0201]  213.01 19.99 90 bottom
RH25  49.9_0201_1%  [R_0201]  214.92 19.99 90 bottom
RH26  49.9_0201_1%  [R_0201]  213.65 19.99 90 bottom
RH27  49.9_0201_1%  [R_0201]  212.11 21.52 90 bottom
RH39  10K_0201_5%  [R_0201]  182 42.01 180 bottom
RH40  10K_0201_5%  [R_0201]  182 40.11 180 bottom
RH41  10K_0201_5%  [R_0201]  182 40.74 180 bottom
RH42  0_0201_5%  [R0201_0OHM]  169.01 55.81 90 top
RH46  100K_0201_5%  [R_0201]  173.71 55.51 270 top
RH57  0_0201_5%  [R0201_0OHM]  165.07 45.31 90 bottom
RH64  1M_0201_1%  [R_0201]  172.65 46.33 0 bottom
RH80  49.9_0201_1%  [R_0201]  129.19 22.11 270 top
RH95  1K_0201_1%  [R_0201]  125.95 21.16 270 top
RH96  1K_0201_5%  [R_0201]  125.13 19.95 270 top
RH98  20K_0201_5%  [R_0201]  177.93 35.15 180 bottom
RH111  33_0201_1%  [R_0201]  163.74 48.14 270 bottom
RH112  33_0201_1%  [R_0201]  164.31 49.41 270 bottom
RH113  33_0201_1%  [R_0201]  163.7 49.41 270 bottom
RH114  75K_0201_5%  [R_0201]  195.13 56.49 0 top
RH129  10K_0201_5%  [R_0201]  180.6 37.18 180 bottom
RH139  10K_0201_5%  [R_0201]  176.84 37.57 0 top
RH141  100K_0201_5%  [R_0201]  169.01 45.27 90 bottom
RH142  4.7K_0201_5%  [R_0201]  168.4 45.27 90 bottom
RH143  499_0201_1%  [R_0201]  181.86 35.85 0 top
RH144  499_0201_1%  [R_0201]  181.86 36.42 0 top
RH145  10K_0201_5%  [R_0201]  180.6 37.95 180 bottom
RH185  10K_0201_5%  [R_0201]  176.84 35.85 0 top
RH200  10K_0201_5%  [R_0201]  180.6 42.01 180 bottom
RH201  10K_0201_5%  [R_0201]  179.36 42.77 270 bottom
RH202  10K_0201_5%  [R_0201]  184.88 42.77 180 bottom
RH203  10K_0201_5%  [R_0201]  183.1 42.77 0 bottom
RH207  0_0201_5%  [R0201_0OHM]  177.86 46.57 0 top
RH217  1K_0201_1%  [R_0201]  164.94 49.41 270 bottom
RH218  0_0201_5%  [R0201_0OHM]  164.92 50.68 270 bottom
RH280  0_0201_5%  [R0201_0OHM]  176.78 43.47 0 top
RH297  10K_0201_5%  [R_0201]  166.47 50.68 270 top
RH298  100K_0201_5%  [R_0201]  173.71 57.47 90 top
RH300  10K_0201_5%  [R_0201]  172.94 33.63 90 bottom
RH301  4.7K_0201_5%  [R_0201]  173.71 56.78 270 top
RH312  0_0201_5%  [R0201_0OHM]  165.89 50.1 90 top
RH460  100K_0201_5%  [R_0201]  169.01 50.1 90 top
RH475  60.4_0201_1%  [R_0201]  179.38 28.17 0 top
RH565  0_0402_5%  [R0402_0OHM]  199.87 66.32 90 top
RH572  20K_0201_5%  [R_0201]  178.51 50.96 180 top
RH573  20K_0201_5%  [R_0201]  169.9 50.68 270 bottom
RH575  1M_0201_1%  [R_0201]  178.72 48.75 270 top
RH584  0_0201_5%  [R0201_0OHM]  186.62 25.94 0 top
RH586  0_0201_5%  [R0201_0OHM]  188.48 25.94 180 top
RH587  60.4_0201_1%  [R_0201]  170.24 20.8 0 top
RH588  1K_0201_5%  [R_0201]  170.82 19.66 180 top
RH591  100K_0201_5%  [R_0201]  167.86 50.1 90 top
RH592  10K_0201_5%  [R_0201]  168.43 50.1 90 top
RH594  0_0201_5%  [R0201_0OHM]  175.99 34.43 270 bottom
RH595  1K_0201_5%  [R_0201]  157.23 19.91 180 top
RH600  0_0201_5%  [R0201_0OHM]  167.48 48.78 270 bottom
RH601  10K_0201_5%  [R_0201]  166.59 48.19 90 bottom
RH603  10K_0201_5%  [R_0201]  163.42 43.57 270 bottom
RH604  10K_0201_5%  [R_0201]  177.98 28.17 0 top
RH605  10K_0201_5%  [R_0201]  163.42 45.63 270 bottom
RH606  1K_0201_5%  [R_0201]  172.31 34.9 90 bottom
RH607  1K_0201_5%  [R_0201]  170.4 34.9 90 bottom
RH610  10K_0201_5%  [R_0201]  177.93 42.14 180 top
RH612  10K_0201_5%  [R_0201]  182 37.18 180 bottom
RH613  10K_0201_5%  [R_0201]  177.43 36.99 180 top
RH614  10K_0201_5%  [R_0201]  182 37.95 180 bottom
RH615  10K_0201_5%  [R_0201]  177.43 36.42 180 top
RH616  10K_0201_5%  [R_0201]  182 38.71 180 bottom
RH617  20K_0201_5%  [R_0201]  170.02 42.3 270 bottom
RH618  2.2K_0201_5%  [R_0201]  170.66 42.3 270 bottom
RH621  4.7K_0201_5%  [R_0201]  157.07 50.1 90 top
RH622  0_0201_5%  [R0201_0OHM]  142.84 81.53 90 bottom
RH625  0_0201_5%  [R0201_0OHM]  173.71 59.32 270 top
RH629  10K_0201_5%  [R_0201]  177.98 27.53 0 top
RH630  10K_0201_5%  [R_0201]  177.98 26.9 0 top
RH631  10K_0201_5%  [R_0201]  182 41.38 180 bottom
RH632  2.2K_0201_5%  [R_0201]  178.44 45.43 180 top
RH633  2.2K_0201_5%  [R_0201]  178.44 44.85 180 top
RH634  1K_0201_5%  [R_0201]  168.98 44.36 180 bottom
RH635  100K_0201_5%  [R_0201]  165.83 42.81 270 bottom
RH636  100K_0201_5%  [R_0201]  166.47 42.81 270 bottom
RH637  0_0201_5%  [R_0201]  170.11 52.17 0 top
RH638  0_0201_5%  [R0201_0OHM]  171.04 34.9 90 bottom
RH639  0_0201_5%  [R0201_0OHM]  171.67 34.9 90 bottom
RH640  1K_0201_5%  [R_0201]  167.1 45.86 270 bottom
RH641  4.7K_0201_5%  [R_0201]  167.74 45.27 90 bottom
RH643  100K_0201_5%  [R_0201]  165.83 45.27 90 bottom
RH645  0_0201_5%  [R0201_0OHM]  159.99 49.21 90 bottom
RH646  100K_0201_5%  [R_0201]  173.58 35.47 270 bottom
RH647  4.7K_0201_5%  [R_0201]  159.94 50.46 180 bottom
RH653  1K_0201_5%  [R_0201]  178.44 47.14 180 top
RH654  0_0201_5%  [R_0201]  187.51 36.93 0 top
RH655  100K_0201_5%  [R_0201]  186.82 36.93 180 top
RH658  100K_0201_5%  [R_0201]  176.84 35.28 0 top
RH659  0_0201_5%  [R0201_0OHM]  160.62 42.99 90 bottom
RH660  100K_0201_5%  [R_0201]  177.98 24.99 0 top
RH661  4.7K_0201_5%  [R_0201]  177.98 25.63 0 top
RH665  10K_0201_5%  [R_0201]  180.6 38.71 180 bottom
RH666  4.7K_0201_5%  [R_0201]  178.62 35.15 0 bottom
RH667  8.2K_0201_5%  [R_0201]  159.35 45.6 270 bottom
RH671  10K_0201_1%  [R_0201]  177.67 51.54 0 top
RH672  10K_0201_5%  [R_0201]  164.31 43.57 270 bottom
RH675  100K_0201_5%  [R_0201]  177.98 26.27 0 top
RH682  100K_0201_5%  [R_0201]  174.15 52.84 270 top
RH683  100K_0201_5%  [R_0201]  174.72 52.84 270 top
RH684  100K_0201_5%  [R_0201]  173.51 52.84 270 top
RH685  100K_0201_5%  [R_0201]  175.86 52.84 270 top
RH686  100K_0201_5%  [R_0201]  176.44 52.84 270 top
RH687  100K_0201_5%  [R_0201]  166.41 44.06 90 bottom
RH688  100K_0201_5%  [R_0201]  163.14 48.83 90 bottom
RH689  100K_0201_5%  [R_0201]  161.26 45.02 90 bottom
RH690  100K_0201_5%  [R_0201]  160.24 50.68 270 top
RH691  100K_0201_5%  [R_0201]  175.29 52.84 270 top
RH692  4.7K_0201_5%  [R_0201]  171.67 36.13 90 bottom
RH705  33_0201_5%  [R_0201]  174.4 54.38 90 bottom
RH706  33_0201_5%  [R_0201]  173.83 54.38 90 bottom
RH709  100K_0201_5%  [R_0201]  160.62 45.02 90 bottom
RH713  100K_0201_5%  [R_0201]  173.58 33.63 90 bottom
RH715  0_0201_5%  [R_0201]  182 42.77 180 bottom
RH716  0_0201_5%  [R_0201]  180.02 42.77 0 bottom
RH717  100K_0201_5%  [R_0201]  165.2 42.81 270 bottom
RH718  100K_0201_5%  [R_0201]  162.53 43.57 270 bottom
RH719  4.99_0201_1%  [R_0201]  213.27 21.52 90 bottom
RH720  4.99_0201_1%  [R_0201]  215.93 21.52 90 bottom
RH721  4.99_0201_1%  [R_0201]  215.17 21.52 90 bottom
RH722  4.99_0201_1%  [R_0201]  213.9 21.52 90 bottom
RH723  4.99_0201_1%  [R_0201]  212.69 21.52 90 bottom
RH724  20K_0201_5%  [R_0201]  194.06 57.5 180 bottom
RH725  20K_0201_5%  [R_0201]  194.06 56.23 180 bottom
RH727  10K_0201_5%  [R_0201]  175.5 44.57 225 bottom
RH728  10K_0201_5%  [R_0201]  196.18 59.03 0 top
RH729  0_0201_5%  [R0201_0OHM]  177.77 63.31 90 bottom
RH730  0_0201_5%  [R_0201]  177.86 46 0 top
RH731  0_0201_5%  [R_0201]  177.86 44.3 0 top
RH732  0_0201_5%  [R_0201]  184.4 34.07 0 top
RH733  100K_0201_5%  [R_0201]  175.9 56.16 180 top
RH734  0_0201_5%  [R_0201]  55.08 12.42 180 top
RH735  0_0201_5%  [R0201_0OHM]  214.54 21.52 90 bottom
RH736  0_0201_5%  [R0201_0OHM]  216.54 21.52 90 bottom
RH737  0_0201_5%  [R0201_0OHM]  160.43 46.81 180 bottom
RH738  100K_0201_5%  [R_0201]  157.89 50.11 0 bottom
RH739  100K_0201_5%  [R_0201]  157.89 49.46 0 bottom
RH740  100K_0201_5%  [R_0201]  156.69 50.11 0 bottom
RH741  100K_0201_5%  [R_0201]  156.69 49.46 0 bottom
RH742  10K_0201_5%  [R_0201]  161.89 43.57 270 bottom
RH743  0_0201_5%  [R_0201]  219.88 47.93 0 top
RH744  0_0201_5%  [R0201_0OHM]  221.11 48.37 270 top
RH745  100K_0201_5%  [R_0201]  179.19 43.47 0 top
RH746  100K_0201_5%  [R_0201]  178.57 43.47 180 top
RH747  100K_0201_5%  [R_0201]  180.98 43.34 180 top
RH748  100K_0201_5%  [R_0201]  179.04 46.05 270 top
RH749  75K_0201_5%  [R_0201]  175.53 36.93 0 bottom
RM1  0_0201_5%  [R0201_0OHM]  19.27 54.93 90 top
RM2  0_0201_5%  [R0201_0OHM]  12 55.98 0 top
RM9  0_0201_5%  [R0201_0OHM]  14.32 57.81 90 top
RM10  0_0201_5%  [R0201_0OHM]  16.76 57.82 0 top
RM11  0_0201_5%  [R0201_0OHM]  270.01 55.73 180 top
RM12  0_0201_5%  [R0201_0OHM]  270.01 58.27 180 top
RM13  0_0201_5%  [R0201_0OHM]  14.89 58.39 270 top
RM14  0_0201_5%  [R0201_0OHM]  17.34 58.39 180 top
RM15  0_0201_5%  [R0201_0OHM]  269.42 56.36 0 top
RM16  0_0201_5%  [R0201_0OHM]  269.42 57.63 0 top
RM17  0_0201_5%  [R0201_0OHM]  269.42 58.9 0 top
RM18  0_0201_5%  [R0201_0OHM]  269.42 55.09 0 top
RM19  0_0201_5%  [R0201_0OHM]  12.67 54.49 270 top
RM20  0_0201_5%  [R0201_0OHM]  12.1 54.49 270 top
RM21  0_0201_5%  [R0201_0OHM]  272.7 53.8 270 top
RM22  0_0201_5%  [R0201_0OHM]  272.13 53.8 270 top
RPD11  3.3K_0201_5%  [R_0201]  20.29 21.52 135 bottom
RPD12  3.3K_0201_5%  [R_0201]  19.27 18.21 135 bottom
RPD13  3.3K_0201_5%  [R_0201]  10.91 27.52 225 bottom
RPD14  3.3K_0201_5%  [R_0201]  18.46 17.41 135 bottom
RPD17  0_0201_5%  [R0201_0OHM]  20.31 19.99 225 top
RPD21  0_0201_5%  [R0201_0OHM]  12.25 36.74 0 bottom
RPD22  0_0201_5%  [R0201_0OHM]  12.25 37.37 0 bottom
RPD59  3.3K_0201_5%  [R_0201]  243.53 12.13 90 bottom
RPD60  3.3K_0201_5%  [R_0201]  243.53 11.31 270 bottom
RPD61  3.3K_0201_5%  [R_0201]  232.76 10.37 270 bottom
RPD62  3.3K_0201_5%  [R_0201]  243.53 9.79 270 bottom
RPD84  0_0402_5%  [R0402_0OHM]  8.15 15.18 45 top
RPD88  0_0201_5%  [R0201_0OHM]  11.24 26.61 135 top
RPD89  10K_0201_1%  [R_0201]  276.26 8.39 270 top
RPD90  100K_0201_1%  [R_0201]  10.57 15.96 225 top
RPD91  300K_0201_1%  [R_0201]  9.1 15.17 225 top
RPD92  100K_0201_1%  [R_0201]  9.94 14.36 135 top
RPD93  0_0402_5%  [R0402_0OHM]  273.3 14.6 0 top
RPD96  0_1206_5%  [R1206_0OHM]  274.09 18.57 0 top
RPD97  0_0201_5%  [R0201_0OHM]  284.37 18.59 90 top
RPD99  100K_0201_1%  [R_0201]  276.89 7.81 90 top
RPD100  100K_0201_1%  [R_0201]  9.76 15.95 45 top
RPD101  300K_0201_1%  [R_0201]  273.87 13.36 180 top
RPD102  100K_0201_1%  [R_0201]  273.87 12.18 90 top
RPD105  0_0201_5%  [R0201_0OHM]  287 11.39 0 top
RPD106  0_0201_5%  [R0201_0OHM]  287 12.03 0 top
RPD109  0_0201_5%  [R0201_0OHM]  287.01 9.88 0 top
RPD112  0_0201_5%  [R0201_0OHM]  20.25 22.04 315 top
RPD113  0_0201_5%  [R0201_0OHM]  287 12.66 0 top
RPD114  0_0201_5%  [R_0201]  7.68 15.74 45 top
RPD115  0_0201_5%  [R_0201]  273.29 13.93 0 top
RPD121  0_1206_5%  [R1206_0OHM]  3.53 20.27 0 top
RPD123  0_0201_5%  [R0201_0OHM]  12.26 26.54 315 top
RPD124  0_0201_5%  [R0201_0OHM]  15.51 14.05 135 top
RPD126  0_0201_5%  [R0201_0OHM]  20.24 21.23 135 top
RPD127  0_0201_5%  [R0201_0OHM]  14.49 27.1 315 top
RPD128  100K_0201_5%  [R_0201]  13.19 26.56 135 top
RPD129  10K_0201_5%  [R_0201]  13.64 27.01 135 top
RPD130  0_0201_5%  [R0201_0OHM]  11.82 26.03 315 top
RPD131  0_0201_5%  [R_0201]  281.83 7.8 90 top
RPD132  0_0201_5%  [R0201_0OHM]  279.12 7.96 90 top
RPD134  0_0201_5%  [R0201_0OHM]  287.6 10.51 180 top
RPD135  0_0201_5%  [R0201_0OHM]  287.54 15.85 180 top
RPD136  100K_0201_5%  [R_0201]  287.54 16.42 180 top
RPD137  10K_0201_5%  [R_0201]  287.54 16.99 180 top
RPD138  0_0201_5%  [R0201_0OHM]  285.01 19.18 270 top
RPD139  0_0201_5%  [R_0201]  16.94 15.13 135 top
RPD141  0_0201_5%  [R_0201]  10.3 24.6 315 top
RPD142  0_0201_5%  [R_0201]  17.75 15.94 135 top
RPD144  0_0201_5%  [R_0201]  281.77 18.59 90 top
RPD146  0_0201_5%  [R_0201]  280.7 7.96 90 top
RPD147  0_0201_5%  [R_0201]  285.64 18.59 90 top
RPD149  0_0201_5%  [R0201_0OHM]  283.74 19.18 270 top
RPD150  0_0201_5%  [R0201_0OHM]  283.1 19.18 270 top
RPD151  0_0201_5%  [R0201_0OHM]  282.47 19.18 270 top
RPD152  0_0201_5%  [R0201_0OHM]  11.28 25.49 315 top
RPD153  0_0201_5%  [R0201_0OHM]  10.29 26.48 315 top
RPD154  0_0201_5%  [R0201_0OHM]  10.74 25.02 315 top
RPD155  0_0201_5%  [R_0201]  18.16 16.34 135 top
RPD157  0_0201_5%  [R0201_0OHM]  287.54 18.71 180 top
RPD163  0_0201_5%  [R0201_0OHM]  12.25 35.47 0 bottom
RPD164  0_0201_5%  [R0201_0OHM]  12.25 36.1 0 bottom
RPD165  0_0201_5%  [R0201_0OHM]  284.63 8.45 270 top
RPD166  0_0201_5%  [R0201_0OHM]  285.26 8.45 270 top
RPD167  1M_0201_5%  [R_0201]  278.54 7.96 90 top
RPD168  10K_0201_5%  [R_0201]  277.97 7.96 90 top
RPD169  1M_0201_5%  [R_0201]  15.1 13.65 135 top
RPD170  10K_0201_5%  [R_0201]  14.44 13.42 315 top
RPD171  0_0201_5%  [R0201_0OHM]  280.56 19.18 270 top
RPD172  0_0201_5%  [R0201_0OHM]  8.58 24.84 315 top
RPD173  0_0201_5%  [R_0201]  279.93 19.18 270 top
RPD174  0_0201_5%  [R_0201]  9.44 23.73 315 top
RPD177  100K_0201_5%  [R_0201]  279.29 18.59 90 top
RPD181  10K_0201_5%  [R_0201]  16.88 25.45 225 top
RPD182  10K_0201_5%  [R_0201]  287.59 14.44 180 top
RPD183  10K_0201_5%  [R_0201]  15.38 26.25 45 top
RPD184  10K_0201_5%  [R_0201]  287.54 17.56 180 top
RPD185  0_0201_5%  [R0201_0OHM]  16.24 26.21 225 top
RPD186  0_0201_5%  [R0201_0OHM]  288.17 15.21 180 top
RPD187  0_0201_5%  [R0201_0OHM]  16.49 14.68 135 top
RPD188  0_0201_5%  [R0201_0OHM]  276.26 9.56 270 top
RPD189  10K_0201_5%  [R_0201]  8.55 23.98 135 top
RPD190  100K_0201_5%  [R_0201]  15.68 14.69 315 top
RPD191  100K_0201_5%  [R_0201]  11.7 27.12 135 top
RPD192  100K_0201_5%  [R_0201]  286.95 19.28 0 top
RPD193  100K_0201_5%  [R_0201]  276.89 8.98 90 top
RPD194  0_0201_5%  [R_0201]  17.35 15.53 135 top
RPD196  10K_0201_5%  [R_0201]  18.63 15.88 315 top
RPD197  10K_0201_5%  [R_0201]  18.22 15.46 315 top
RPD198  10K_0201_5%  [R_0201]  17.8 15.04 315 top
RPD199  0_0201_5%  [R_0201]  280.13 7.96 90 top
RPD201  10K_0201_5%  [R_0201]  280.7 8.74 90 bottom
RPD202  10K_0201_5%  [R_0201]  281.27 8.38 270 top
RPD203  10K_0201_5%  [R_0201]  280.13 8.74 90 bottom
RPD204  0_0201_5%  [R_0201]  9.85 24.14 315 top
RPD205  0_0201_5%  [R_0201]  281.21 18.6 90 top
RR1  6.2K_0402_1%  [R_0402]  275.42 23.79 0 top
RR2  0_0201_5%  [R0201_0OHM]  283.65 23.34 0 top
RR3  0_0201_5%  [R0201_0OHM]  283.65 23.98 0 top
RR4  0_0201_5%  [R0201_0OHM]  283.65 24.74 0 top
RR6  0_0201_5%  [R0201_0OHM]  283.65 26.01 0 top
RR8  0_0201_5%  [R0201_0OHM]  283.65 26.64 0 top
RR9  0_0201_5%  [R0201_0OHM]  283.65 27.28 0 top
RR10  10K_0201_1%  [R_0201]  280.39 30.87 270 top
RR11  10K_0201_1%  [R_0201]  277.97 30.87 270 top
RR12  0_0201_5%  [R0201_0OHM]  278.61 30.87 270 top
RS200  0_0805_5%  [R_0805]  219.49 8.57 270 top
RS207  0_0201_5%  [R_0201]  205.77 15.25 270 bottom
RS208  0_0201_5%  [R_0201]  205.14 15.25 270 bottom
RS377  10K_0201_5%  [R_0201]  205.18 4.48 180 top
RS378  0_0201_5%  [R_0201]  216.94 12.63 270 top
RT1  1M_0201_1%  [R_0201]  17.15 46.96 180 bottom
RT2  1M_0201_1%  [R_0201]  17.15 45.06 180 bottom
RT3  1M_0201_1%  [R_0201]  285.93 38.2 0 top
RT4  1M_0201_1%  [R_0201]  285.93 37.57 0 top
RT6  10K_0201_5%  [R_0201]  9.44 50.37 0 top
RT7  100_0201_1%  [R_0201]  8.4 40.94 90 top
RT8  10K_0201_5%  [R_0201]  4.63 48.46 180 top
RT9  10K_0201_5%  [R_0201]  5.34 48.46 0 top
RT10  100K_0201_5%  [R_0201]  5.34 44.96 0 top
RT11  10K_0201_5%  [R_0201]  5.34 47.88 0 top
RT12  10K_0201_5%  [R_0201]  4.63 47.88 180 top
RT13  10K_0201_5%  [R_0201]  4.63 45.54 180 top
RT14  10K_0201_5%  [R_0201]  5.34 45.54 0 top
RT15  10K_0201_5%  [R_0201]  5.96 43.75 90 top
RT16  10K_0201_5%  [R_0201]  3.45 45.54 90 top
RT17  10K_0201_5%  [R_0201]  5.34 46.12 0 top
RT18  10K_0201_5%  [R_0201]  4.63 46.12 180 top
RT19  4.75K_0402_0.5%  [R_0402]  13.81 45.01 270 bottom
RT20  2.2K_0201_1%  [R_0201]  9.02 30.71 180 bottom
RT21  2.2K_0201_1%  [R_0201]  9.02 30.07 180 bottom
RT22  3.32K_0201_1%  [R_0201]  10.55 30.71 180 bottom
RT23  3.32K_0201_1%  [R_0201]  18.57 32.07 90 top
RT30  100_0201_1%  [R_0201]  276.45 32.83 90 top
RT33  100K_0201_5%  [R_0201]  275.09 39.34 180 top
RT34  10K_0201_5%  [R_0201]  275.09 38.77 180 top
RT35  10K_0201_5%  [R_0201]  275.09 38.2 180 top
RT36  10K_0201_5%  [R_0201]  275.22 32.46 180 top
RT37  10K_0201_5%  [R_0201]  275.22 33.03 180 top
RT38  10K_0201_5%  [R_0201]  275.22 33.6 180 top
RT39  10K_0201_5%  [R_0201]  275.22 34.17 180 top
RT40  10K_0201_5%  [R_0201]  275.22 34.75 180 top
RT41  10K_0201_5%  [R_0201]  275.22 35.32 180 top
RT42  2.2K_0201_1%  [R_0201]  247.4 17.63 180 top
RT43  2.2K_0201_1%  [R_0201]  247.4 16.74 180 top
RT44  3.32K_0201_1%  [R_0201]  247.4 15.67 180 top
RT45  3.32K_0201_1%  [R_0201]  259.18 17.04 90 top
RT50  4.75K_0402_0.5%  [R_0402]  282.29 37.13 270 bottom
RT53  0_0201_5%  [R_0201]  15.93 47.23 0 top
RT54  0_0201_5%  [R_0201]  17.72 47.23 180 top
RT55  0_0201_5%  [R_0201]  284.16 40.55 0 top
RT56  0_0201_5%  [R_0201]  284.16 39.91 0 top
RT59  0_0201_5%  [R0201_0OHM]  5.34 49.05 0 top
RT62  0_0201_5%  [R0201_0OHM]  275.34 38.2 180 bottom
RT63  10K_0201_5%  [R_0201]  10.43 41.46 0 bottom
RT64  10K_0201_5%  [R_0201]  10.61 43.09 0 bottom
RT65  10K_0201_5%  [R_0201]  10.43 40.87 0 bottom
RT71  10K_0201_5%  [R_0201]  275.05 29.79 270 top
RT72  10K_0201_5%  [R_0201]  276.58 29.73 270 top
RT73  10K_0201_5%  [R_0201]  275.81 29.79 270 top
RT79  0_0402_5%  [R0402_0OHM]  13.1 36.93 0 top
RT83  0_0201_5%  [R0201_0OHM]  18.54 39.85 0 top
RT84  0_0201_5%  [R_0201]  18.54 40.49 0 top
RT88  0_0402_5%  [R0402_0OHM]  286.99 34.82 90 top
RT93  100K_0201_5%  [R_0201]  289.31 26.64 180 top
RT94  0_0201_5%  [R0201_0OHM]  288.73 25.37 0 top
RT95  0_0201_5%  [R_0201]  288.73 24.74 0 top
RT97  10K_0201_5%  [R_0201]  10.43 42.05 0 bottom
RT98  10K_0201_5%  [R_0201]  274.42 29.73 270 top
RT101  0_0201_5%  [R_0201]  10.03 49.78 180 top
RT102  0_0201_5%  [R_0201]  275.9 42.13 270 top
RT109  10K_0201_5%  [R_0201]  8.86 50.37 270 top
RT112  0_0201_5%  [R0201_0OHM]  14.76 40.96 90 top
RT113  0_0201_5%  [R0201_0OHM]  14.19 40.96 90 top
RT116  0_0201_5%  [R0201_0OHM]  284.23 38.33 180 top
RT117  0_0201_5%  [R0201_0OHM]  284.23 38.96 180 top
RT118  1M_0201_1%  [R_0201]  12.21 61.16 270 top
RT119  1M_0201_1%  [R_0201]  13.24 66.99 90 top
RT120  1M_0201_1%  [R_0201]  273.05 62.21 0 bottom
RT121  1M_0201_1%  [R_0201]  272.19 62.84 180 bottom
RT122  0_0201_5%  [R_0201]  13.01 45.69 0 bottom
RT123  0_0201_5%  [R_0201]  280.3 37.06 180 bottom
RT124  0_0201_5%  [R0201_0OHM]  9.53 47.09 180 bottom
RT125  0_0201_5%  [R0201_0OHM]  9.53 46.46 180 bottom
RT150  1M_0201_1%  [R_0201]  10.24 18.38 45 bottom
RT151  1M_0201_1%  [R_0201]  268.18 16.5 90 top
RT152  0_0201_5%  [R0201_0OHM]  18.68 46.14 180 top
RT158  10K_0201_5%  [R_0201]  289.31 26.01 180 top
RT159  0_0201_5%  [R_0201]  4.63 47.29 180 top
RT160  0_0201_5%  [R_0201]  4.63 46.71 180 top
RT162  0_0201_5%  [R_0201]  4.63 49.05 180 top
RT163  0_0201_5%  [R_0201]  275.34 37.57 180 bottom
RT164  0_0201_5%  [R0201_0OHM]  17.15 46.33 180 bottom
RT165  0_0201_5%  [R0201_0OHM]  17.15 45.69 180 bottom
RT166  0_0201_5%  [R0201_0OHM]  287.79 37.57 180 top
RT167  0_0201_5%  [R0201_0OHM]  287.79 38.2 180 top
RT168  0_0201_5%  [R0201_0OHM]  10.66 37.25 0 top
RT169  0_0201_5%  [R_0201]  12.83 32.68 180 bottom
RT170  0_0201_5%  [R_0201]  232.76 12.91 270 bottom
RT171  0_0201_5%  [R0201_0OHM]  289.06 34.14 180 top
RT172  10K_0201_5%  [R_0201]  4.63 44.96 180 top
RT173  10K_0201_5%  [R_0201]  275.09 39.91 180 top
RT174  0_0201_5%  [R_0201]  9.66 37.31 180 top
RT175  0_0201_5%  [R_0201]  287.98 24.74 180 top
RT176  0_0201_5%  [R_0201]  10.88 39.67 90 bottom
RT177  0_0201_5%  [R_0201]  274.42 27.87 90 top
RT178  100K_0201_5%  [R_0201]  19.12 38.58 180 top
RT179  10K_0201_5%  [R_0201]  19.12 39.22 180 top
RT180  0_0402_5%  [R0402_0OHM]  9.44 45.69 180 bottom
RT181  0_0402_5%  [R0402_0OHM]  9.44 44.87 180 bottom
RT184  0_0402_5%  [R0402_0OHM]  287.75 35.74 270 top
RT185  0_0402_5%  [R0402_0OHM]  286.23 35.74 270 top
RT186  0_0201_5%  [R_0201]  8.29 50.37 270 top
RT187  0_0201_5%  [R_0201]  275.34 39.72 180 bottom
RT189  10K_0201_5%  [R_0201]  275.09 40.49 180 top
RT190  10K_0201_5%  [R_0201]  275.09 41.06 180 top
RT193  100K_0201_5%  [R_0201]  5.34 47.29 0 top
RT194  100K_0201_5%  [R_0201]  5.34 46.71 0 top
RT195  100K_0201_5%  [R_0201]  275.34 36.49 180 top
RT196  100K_0201_5%  [R_0201]  275.34 37.06 180 top
RT197  0_0201_5%  [R0201_0OHM]  277.38 38.9 180 bottom
RT198  0_0201_5%  [R0201_0OHM]  277.38 38.33 180 bottom
RT199  0_0201_5%  [R0201_0OHM]  275.32 41.63 180 top
RT200  0_0201_5%  [R_0201]  275.34 37.63 180 top
RT201  0_0201_5%  [R_0201]  275.34 35.91 180 top
RT202  0_0201_5%  [R_0201]  288.64 36.84 270 top
RT203  0_0201_5%  [R_0201]  18.09 45.57 0 top
RT212  0_0201_5%  [R_0201]  10.1 47.43 90 bottom
RT213  0_0201_5%  [R_0201]  10.7 47.43 90 bottom
RT214  0_0201_5%  [R_0201]  18.7 46.73 90 top
RT215  0_0201_5%  [R_0201]  277.85 39.5 90 bottom
RT216  0_0201_5%  [R_0201]  278.42 39.5 90 bottom
RT217  0_0201_5%  [R_0201]  275.32 42.2 180 top
RT218  10K_0201_5%  [R_0201]  9.07 44.18 180 bottom
RT219  10K_0201_5%  [R_0201]  275.22 31.88 180 top
RT222  10K_0201_5%  [R_0201]  11.32 35.99 90 top
RT223  100K_0201_5%  [R_0201]  10.69 36.57 270 top
RT224  10K_0201_5%  [R_0201]  287.74 23.96 0 top
RT225  100K_0201_5%  [R_0201]  287.74 23.33 0 top
RTCD2  -  [LBAT54HT1G_SOD323-2]  176.78 8.1 0 top
RTCD3  -  [RB520SM-30T2R_EMD2-2]  171.91 12.52 90 top
RTCD4  -  [LBAT54HT1G_SOD323-2]  50.1 10.27 0 top
RTCD5  -  [LBAT54HT1G_SOD323-2]  176.78 9.82 0 top
RTCD6  -  [BAT54HT1G_SOD323-2]  50.1 11.92 0 top
RTCR1  1.3K_0402_5%  [R_0402]  53.23 13.07 270 top
RTCR2  100K_0201_5%  [R_0201]  54.5 13 0 top
RTCR3  100K_0201_5%  [R_0201]  53.9 12.94 270 top
RTCR4  100K_0201_5%  [R_0201]  179.79 19.72 0 top
RW1  10K_0201_1%  [R_0201]  196.44 61.99 270 bottom
RW4  0_0402_5%  [R_0402]  195.94 67.22 180 top
RW5  0_0402_5%  [R_0402]  195.94 66.46 180 top
RW6  0_0402_5%  [R_0402]  183.52 52.42 90 top
RW7  0_0402_5%  [R_0402]  182.63 52.42 90 top
RW8  0_0201_5%  [R0201_0OHM]  178.7 58.9 180 bottom
RW13  0_0201_5%  [R0201_0OHM]  195.13 57.12 0 top
RW15  0_0201_5%  [R_0201]  196.16 65.7 180 top
RW17  0_0201_5%  [R0201_0OHM]  195.59 59.03 180 top
